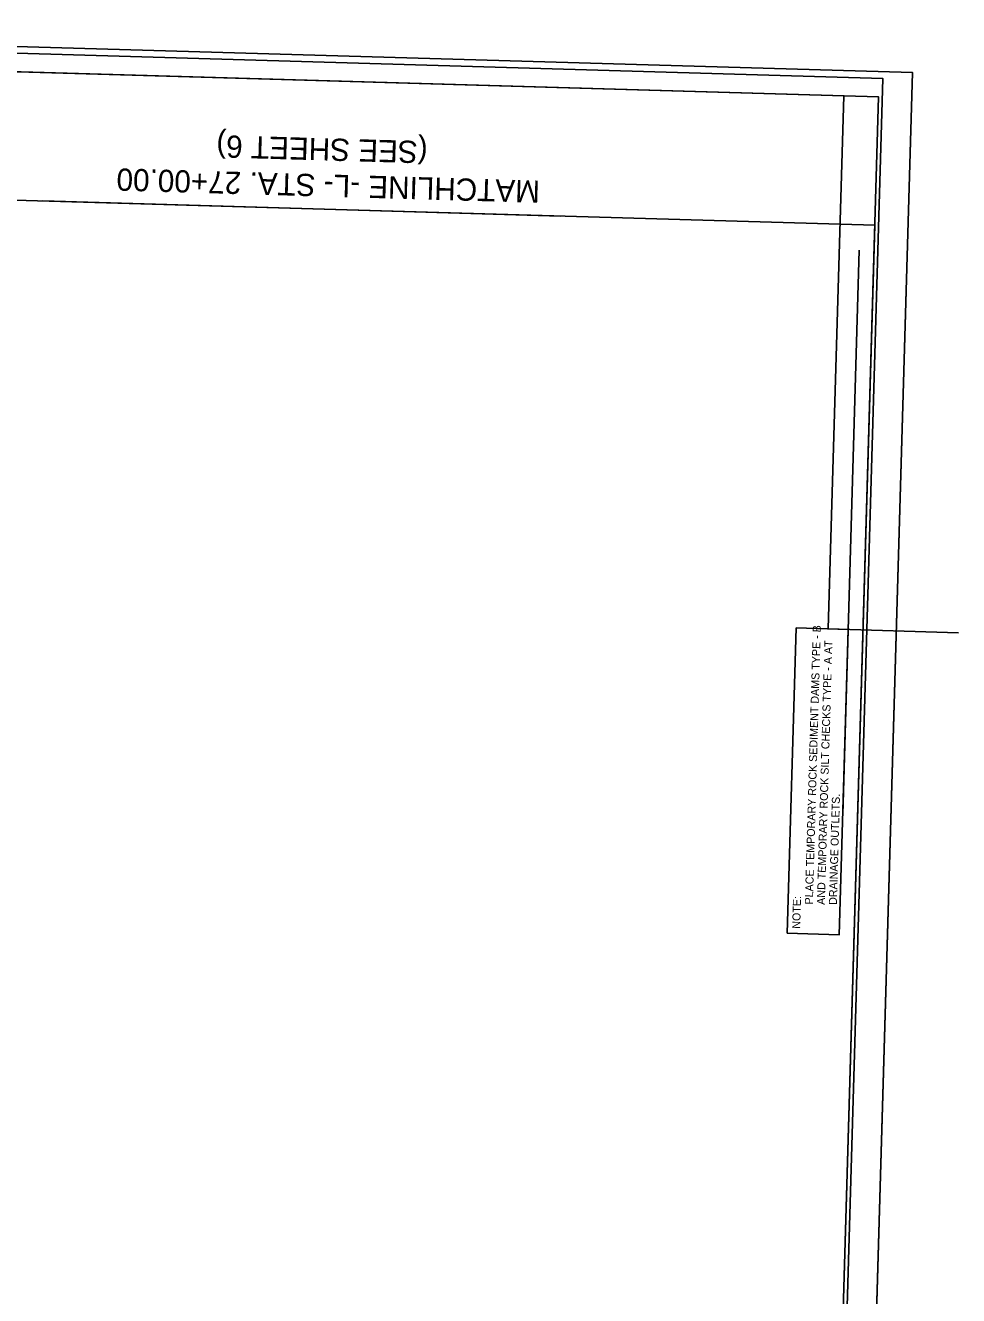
# Model space of a CAD drawing. Extents: x 2096987 to 2098161, y 681809 to 686842.
# Drawn here: x 2097531 to 2098161, y 685985 to 686842 of the extents above; entities that cross this region are included whole.
import ezdxf

# ---------------------------------------------------------------- set-up
doc = ezdxf.new("R2010")
doc.units = 0
for name, color, linetype in [('Construction Sheet Number Note CG CELL', 7, 'Continuous'), ('Matchline', 7, 'Continuous'), ('Prop North Arrow NAD83 for Plan Sheets CELL', 7, 'Continuous'), ('Scratch_Level_0', 7, 'Continuous'), ('Sheet Block Title CELL', 7, 'Continuous'), ('Sheet Data Field CELL', 7, 'Continuous'), ('Sheet Plan And Profile CELL', 7, 'Continuous'), ('Sheet Plot Border Inside CELL', 7, 'Continuous'), ('Sheet Sticker Exception Certification CELL', 7, 'Continuous')]:
    doc.layers.add(name, color=color, linetype=linetype)

msp = doc.modelspace()

# ---------------------------------------------------------------- linework, layer by layer
at = {"layer": 'Construction Sheet Number Note CG CELL'}
msp.add_lwpolyline([(2098045.73, 686229.75), (2098051.72, 686435.74), (2098086.81, 686434.72), (2098080.84, 686228.73)], close=True, dxfattribs=at)
at = {"layer": 'Prop North Arrow NAD83 for Plan Sheets CELL'}
msp.add_line((2097543.06, 686723.93), (2097892.91, 686713.76), dxfattribs=at)
at = {"layer": 'Scratch_Level_0'}
msp.add_line((2098083.18, 686309.88), (2098094.25, 686690.63), dxfattribs=at)
msp.add_lwpolyline([(2098083.77, 686794.96), (2098073.31, 686435.11), (2098161.37, 686432.55)], dxfattribs=at)
at = {"layer": 'Sheet Block Title CELL'}
msp.add_lwpolyline([(2098081.34, 685127.82), (2098130.26, 686810.61), (2097035.73, 686842.43), (2096986.81, 685159.64)], close=True, dxfattribs=at)
at = {"layer": 'Sheet Data Field CELL'}
msp.add_lwpolyline([(2098061.73, 685141.4), (2098110.13, 686806.68), (2097055.59, 686837.35), (2097007.18, 685172.06)], close=True, dxfattribs=at)
at = {"layer": 'Sheet Plan And Profile CELL'}
msp.add_line((2098081.34, 685127.82), (2098130.26, 686810.61), dxfattribs=at)
at = {"layer": 'Sheet Plot Border Inside CELL'}
msp.add_lwpolyline([(2098075.38, 685697.44), (2097236.74, 685318.87), (2097014.12, 685325.38), (2097045.97, 686421.2), (2097047.21, 686463.77), (2097051.88, 686624.82), (2097288.1, 686617.97), (2097291.39, 686731.15), (2098104.74, 686707.51)], close=True, dxfattribs=at)
msp.add_lwpolyline([(2098075.38, 685697.44), (2097236.74, 685318.87), (2097014.12, 685325.38), (2097045.97, 686421.2), (2097047.21, 686463.77), (2097051.88, 686624.82), (2097288.1, 686617.97), (2097291.39, 686731.15), (2098104.74, 686707.51)], close=True, dxfattribs=at)
at = {"layer": 'Sheet Sticker Exception Certification CELL'}
for points in [[(2097057.71, 686824.81), (2097014.12, 685325.41), (2098063.68, 685294.9), (2098107.27, 686794.27)], [(2098063.68, 685294.9), (2097014.15, 685325.38), (2097051.88, 686624.82), (2097201.88, 686620.47), (2097207.71, 686820.43), (2098107.27, 686794.27)]]:
    msp.add_lwpolyline(points, close=True, dxfattribs=at)

# ---------------------------------------------------------------- texts
at = {"layer": 'Construction Sheet Number Note CG CELL'}
for s, p in [('PLACE TEMPORARY ROCK SEDIMENT DAMS TYPE - B', (2098062.95, 686249.03)), ('AND TEMPORARY ROCK SILT CHECKS TYPE - A AT', (2098071.04, 686248.8)), ('DRAINAGE OUTLETS.', (2098079.15, 686248.78)), ('NOTE:', (2098054.37, 686232.66))]:
    msp.add_text(s, height=5.4, rotation=88.34013, dxfattribs=at).set_placement(p)
at = {"layer": 'Matchline'}
for s, p in [('(SEE SHEET 6)', (2097803.06, 686764.26)), ('MATCHLINE -L- STA. 27+00.00', (2097878.9, 686737.67))]:
    msp.add_text(s, height=15, rotation=178.33483, dxfattribs=at).set_placement(p)

doc.saveas('drawing.dxf')
